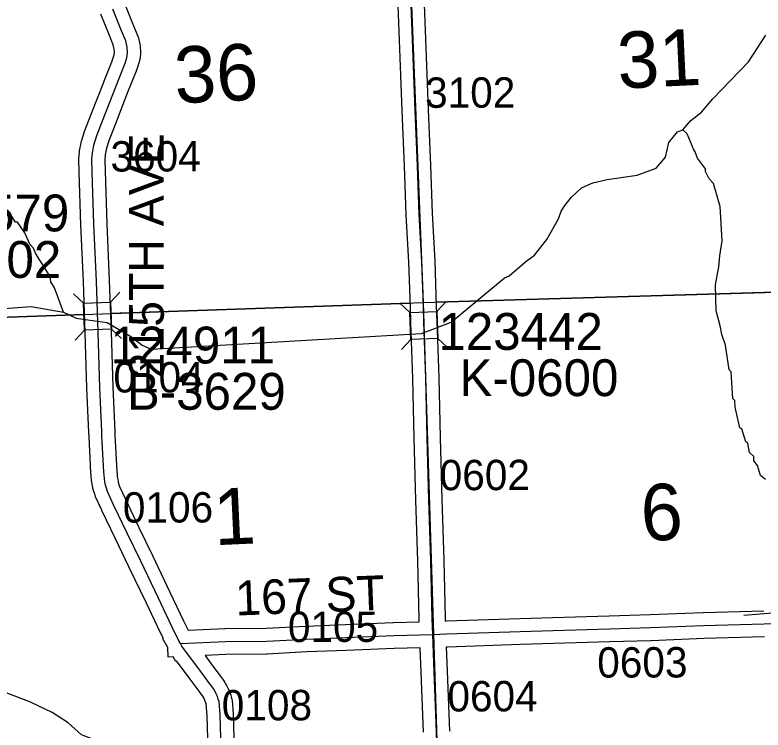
# Model space of a CAD drawing. Extents: x 128.7 to 185.5, y -21.4 to 12.6.
# Drawn here: x 145.06 to 146.785, y -2.33 to -0.681 of the extents above; entities that cross this region are included whole.
import ezdxf

# ---------------------------------------------------------------- set-up
doc = ezdxf.new("R2010")
doc.units = 0
for name, color, linetype in [('tdCoHydroRiver', 7, 'Continuous'), ('tdCoSecRdNmbr', 7, 'Continuous'), ('tdCoSecRdTxt', 7, 'Continuous'), ('tdCoSecRteBand', 7, 'Continuous'), ('tdCoSecRteCL', 7, 'Continuous'), ('tdCoSectLine', 7, 'Continuous'), ('tdCoSectLinePart', 7, 'Continuous'), ('tdCoSectNmbr', 7, 'Continuous'), ('tdCoStrucSec', 7, 'Continuous'), ('tdCoStrucSecCoName', 7, 'Continuous'), ('tdCoStrucSecFHWANum', 7, 'Continuous'), ('tdCoSurfGravel', 7, 'Continuous'), ('tdCoTwpBndry', 7, 'Continuous'), ('tdCoTwpBndryShd', 7, 'Continuous')]:
    doc.layers.add(name, color=color, linetype=linetype)

msp = doc.modelspace()

# ---------------------------------------------------------------- linework, layer by layer
at = {"layer": 'tdCoHydroRiver'}
for points in [[(145.0233, -1.3591), (145.0973, -1.3536), (145.1719, -1.3669), (145.2007, -1.3801), (145.2494, -1.3872), (145.2721, -1.3904), (145.3284, -1.4233), (145.3527, -1.443), (145.3735, -1.4518), (145.9972, -1.4155), (146.0658, -1.3896), (146.1887, -1.2877), (146.1996, -1.2827), (146.238, -1.2498), (146.258, -1.235), (146.2868, -1.1993), (146.3136, -1.1511), (146.3194, -1.1335), (146.3239, -1.1271), (146.3284, -1.1206), (146.3435, -1.1012), (146.3665, -1.0799), (146.393, -1.068), (146.4259, -1.0606), (146.495, -1.0504), (146.5386, -1.0348), (146.5599, -1.0089), (146.5682, -0.9754), (146.588, -0.9511), (146.6004, -0.946), (146.6187, -0.9249), (146.6433, -0.9051), (146.6691, -0.8743), (146.7515, -0.7895), (146.7921, -0.7282)], [(146.791, -1.7524), (146.7797, -1.7433), (146.7726, -1.7199), (146.7643, -1.7091), (146.764, -1.6997), (146.7543, -1.6905), (146.7504, -1.6686), (146.7455, -1.6656), (146.7367, -1.6359), (146.7319, -1.6329), (146.7208, -1.5859), (146.7203, -1.5701), (146.7154, -1.5655), (146.7118, -1.5041), (146.707, -1.4995), (146.6988, -1.443), (146.6901, -1.418), (146.6863, -1.3977), (146.6772, -1.3632), (146.6753, -1.3033), (146.6834, -1.262), (146.6857, -1.2367), (146.6909, -1.2018), (146.6867, -1.1231), (146.6708, -1.0699), (146.6609, -1.0592), (146.6525, -1.0421), (146.6523, -1.0358), (146.6341, -1.0112), (146.6289, -0.9971), (146.6256, -0.9925), (146.6102, -0.9551), (146.6004, -0.946)], [(145.1719, -1.3669), (145.1511, -1.3108), (145.1427, -1.2968), (145.1407, -1.2843), (145.1075, -1.2317), (145.1023, -1.2193), (145.0941, -1.2101), (145.0822, -1.1836), (145.0656, -1.1589), (145.0609, -1.1591), (145.0442, -1.1328)], [(146.7413, -2.065), (146.8074, -2.0596)], [(145.5048, -2.4228), (145.3677, -2.4304), (145.3597, -2.4275), (145.3461, -2.398), (145.33, -2.3859), (145.2133, -2.3408), (145.1824, -2.3134), (145.1453, -2.2894), (145.0956, -2.2657), (144.9806, -2.2222)]]:
    msp.add_lwpolyline(points, dxfattribs=at)
at = {"layer": 'tdCoSecRteBand'}
for points in [[(145.313, -0.6567), (145.3332, -0.7062), (145.3333, -0.7062), (145.3333, -0.7062), (145.3429, -0.7299), (145.3437, -0.7321), (145.3443, -0.7343), (145.3477, -0.7488), (145.3483, -0.7514), (145.3485, -0.754), (145.3492, -0.7669), (145.3494, -0.7697), (145.349, -0.7725), (145.3475, -0.7838), (145.3472, -0.7865), (145.3464, -0.7891), (145.3424, -0.8014), (145.3423, -0.8019), (145.3421, -0.8023), (145.3394, -0.8099), (145.3392, -0.8106), (145.3389, -0.8112), (145.32, -0.8578), (145.2913, -0.9321), (145.2912, -0.9321), (145.2912, -0.9322), (145.2768, -0.9689), (145.2708, -0.9883), (145.2679, -1.0039), (145.2672, -1.0145), (145.2676, -1.0418), (145.2718, -1.1628), (145.2772, -1.2936), (145.2772, -1.2937), (145.2772, -1.2938), (145.2814, -1.4119), (145.2814, -1.4119), (145.2814, -1.412), (145.2856, -1.5389), (145.2898, -1.6414), (145.2903, -1.6509), (145.2947, -1.7329), (145.2947, -1.7332), (145.2948, -1.7334), (145.295, -1.7403), (145.2956, -1.7463), (145.2965, -1.7523), (145.2977, -1.7582), (145.2993, -1.764), (145.3009, -1.7689), (145.3144, -1.798), (145.3456, -1.8634), (145.3766, -1.928), (145.3767, -1.928), (145.3767, -1.928), (145.4169, -2.0118), (145.4169, -2.0119), (145.4169, -2.0119), (145.4486, -2.0782), (145.4593, -2.0999)], [(145.4593, -2.0999), (145.5437, -2.0961), (145.5441, -2.0961), (145.5446, -2.0961), (145.6387, -2.0949), (145.7302, -2.0902), (145.7303, -2.0902), (145.7305, -2.0902), (145.8222, -2.0865), (145.9322, -2.082), (145.9324, -2.082), (145.9326, -2.082), (145.9921, -2.0804), (145.9918, -2.0739), (145.9918, -2.0736), (145.9918, -2.0733), (145.9891, -1.9405), (145.9844, -1.8002), (145.9844, -1.8001), (145.9844, -1.8), (145.9802, -1.6573), (145.9802, -1.6571), (145.9802, -1.657), (145.9775, -1.5194), (145.9728, -1.3901), (145.9728, -1.3901), (145.9728, -1.39), (145.9717, -1.3547), (145.9684, -1.2515), (145.9622, -1.1422), (145.9622, -1.1419), (145.9622, -1.1416), (145.958, -1.0302), (145.9528, -0.9027), (145.9528, -0.9027), (145.9528, -0.9027), (145.9479, -0.7797), (145.9479, -0.7796), (145.9479, -0.7796), (145.9435, -0.6595)], [(146.0034, -0.6572), (146.0079, -0.7773), (146.0128, -0.9003), (146.018, -1.0278), (146.018, -1.0278), (146.018, -1.0279), (146.0222, -1.1391), (146.0283, -1.2485), (146.0283, -1.2489), (146.0283, -1.2493), (146.0316, -1.3528), (146.0328, -1.388), (146.0375, -1.5174), (146.0375, -1.5177), (146.0375, -1.5179), (146.0402, -1.6556), (146.0444, -1.7982), (146.049, -1.9387), (146.0491, -1.9389), (146.0491, -1.9391), (146.0518, -2.0717), (146.0521, -2.0787)], [(145.5048, -2.3497), (145.5029, -2.2966), (145.5007, -2.2699), (145.5001, -2.2677), (145.4986, -2.2636), (145.4969, -2.2596), (145.4949, -2.2557), (145.4927, -2.252), (145.4902, -2.2484), (145.487, -2.2442), (145.4867, -2.2439), (145.4865, -2.2436), (145.4638, -2.2128), (145.4325, -2.1706), (145.4307, -2.1717), (145.4247, -2.1614), (145.4129, -2.162), (145.4119, -2.1394), (145.4005, -2.1198), (145.4019, -2.119), (145.3947, -2.1047), (145.3946, -2.1045), (145.3945, -2.1043), (145.3627, -2.0378), (145.3226, -1.9539), (145.2915, -1.8893), (145.2915, -1.8893), (145.2915, -1.8893), (145.2601, -1.8237), (145.2601, -1.8235), (145.26, -1.8234), (145.2457, -1.7925), (145.245, -1.7909), (145.2444, -1.7893), (145.242, -1.7819), (145.2417, -1.7811), (145.2415, -1.7803), (145.2395, -1.7729), (145.2393, -1.7721), (145.2391, -1.7712), (145.2376, -1.7637), (145.2374, -1.7629), (145.2373, -1.762), (145.2361, -1.7544), (145.236, -1.7536), (145.2359, -1.7528), (145.2352, -1.7451), (145.2351, -1.7442), (145.2351, -1.7434), (145.2348, -1.7359), (145.2304, -1.654), (145.2304, -1.654), (145.2304, -1.6539), (145.2299, -1.6442), (145.2299, -1.6441), (145.2299, -1.644), (145.2257, -1.5412), (145.2257, -1.5411), (145.2257, -1.541), (145.2215, -1.414), (145.2173, -1.296), (145.2119, -1.1651), (145.2119, -1.165), (145.2119, -1.1649), (145.2077, -1.0436), (145.2077, -1.0433), (145.2077, -1.0431), (145.2072, -1.0142), (145.2071, -1.0129), (145.2072, -1.0115), (145.2082, -0.998), (145.2083, -0.9964), (145.2086, -0.9948), (145.2121, -0.9758), (145.2124, -0.974), (145.213, -0.9723), (145.2199, -0.9501), (145.2202, -0.949), (145.2206, -0.948), (145.2353, -0.9103), (145.2642, -0.8359), (145.2643, -0.8357), (145.2643, -0.8355), (145.2831, -0.7893), (145.2854, -0.7827), (145.2884, -0.7734), (145.2892, -0.7675), (145.2887, -0.7601), (145.2864, -0.7504), (145.2777, -0.7289), (145.2575, -0.6793)], [(146.0521, -2.0787), (146.0553, -2.0786), (146.2239, -2.0732), (146.3001, -2.0707), (146.3002, -2.0707), (146.3002, -2.0707), (146.4304, -2.067), (146.5247, -2.064), (146.6471, -2.0589), (146.6473, -2.0589), (146.6476, -2.0588), (146.7872, -2.0554)], [(146.7886, -2.1154), (146.6493, -2.1188), (146.527, -2.124), (146.5269, -2.124), (146.5267, -2.124), (146.4322, -2.127), (146.4322, -2.127), (146.4322, -2.127), (146.302, -2.1307), (146.2259, -2.1331), (146.2259, -2.1331), (146.2259, -2.1331), (146.0572, -2.1386), (146.0571, -2.1386), (146.0571, -2.1386), (146.0546, -2.1386), (146.0569, -2.1939), (146.0569, -2.194), (146.0569, -2.1941), (146.0621, -2.3329)], [(146.0022, -2.3351), (145.997, -2.1964), (145.9946, -2.1407), (145.9946, -2.1403), (145.9942, -2.1403), (145.9344, -2.142), (145.8246, -2.1464), (145.7331, -2.1501), (145.6412, -2.1548), (145.6407, -2.1548), (145.6401, -2.1548), (145.5459, -2.1561), (145.498, -2.1582), (145.5121, -2.1771), (145.5121, -2.1771), (145.5121, -2.1772), (145.5346, -2.2077), (145.5382, -2.2123), (145.5388, -2.2131), (145.5393, -2.2138), (145.5428, -2.219), (145.5433, -2.2198), (145.5438, -2.2206), (145.547, -2.226), (145.5475, -2.2268), (145.5479, -2.2277), (145.5508, -2.2332), (145.5512, -2.2341), (145.5516, -2.235), (145.5541, -2.2407), (145.5544, -2.2416), (145.5548, -2.2425), (145.5569, -2.2484), (145.5572, -2.2492), (145.5575, -2.2502), (145.5592, -2.2562), (145.56, -2.2591), (145.5603, -2.2621), (145.5627, -2.2924), (145.5628, -2.2931), (145.5628, -2.2937), (145.5648, -2.3477)]]:
    msp.add_lwpolyline(points, dxfattribs=at)
at = {"layer": 'tdCoSecRteCL'}
for points in [[(146.0233, -2.1095), (146.0218, -2.0726), (146.0191, -1.9397), (146.0144, -1.7992), (146.0102, -1.6564), (146.0075, -1.5185), (146.0028, -1.3891), (146.0017, -1.3537), (145.9983, -1.2502), (145.9922, -1.1405), (145.988, -1.029), (145.9828, -0.9015), (145.9779, -0.7785), (145.9734, -0.6584), (145.9683, -0.5286), (145.9653, -0.4071), (145.9628, -0.3451)], [(145.4415, -2.1307), (145.4386, -2.1257), (145.4216, -2.0914), (145.3898, -2.0248), (145.3496, -1.941), (145.3185, -1.8763), (145.2872, -1.8107), (145.2729, -1.7799), (145.2705, -1.7726), (145.2685, -1.7651), (145.2669, -1.7576), (145.2658, -1.7499), (145.2651, -1.7423), (145.2648, -1.7345), (145.2603, -1.6524), (145.2599, -1.6427), (145.2557, -1.54), (145.2515, -1.413), (145.2473, -1.2948), (145.2418, -1.1639), (145.2377, -1.0426), (145.2372, -1.0137), (145.2381, -1.0002), (145.2416, -0.9812), (145.2485, -0.959), (145.2633, -0.9212), (145.2922, -0.8468), (145.3111, -0.7999), (145.3139, -0.7923), (145.3178, -0.7799), (145.3193, -0.7686), (145.3185, -0.7558), (145.3151, -0.7412), (145.3055, -0.7175), (145.2852, -0.668)], [(146.0233, -2.1095), (146.0562, -2.1086), (146.2249, -2.1031), (146.3011, -2.1007), (146.4313, -2.097), (146.5258, -2.094), (146.6483, -2.0888), (146.7879, -2.0854), (146.9452, -2.0819), (147.0195, -2.0804)], [(145.4415, -2.1307), (145.545, -2.1261), (145.6397, -2.1248), (145.7317, -2.1202), (145.8234, -2.1165), (145.9334, -2.112), (146.0233, -2.1095)], [(146.0618, -3.3563), (146.0615, -3.3461), (146.0583, -3.1979), (146.0533, -3.0443), (146.0489, -2.9158), (146.045, -2.7585), (146.0408, -2.6051), (146.0368, -2.4808), (146.0321, -2.334), (146.027, -2.1952), (146.0233, -2.1095)], [(145.5354, -2.3803), (145.5348, -2.3488), (145.5328, -2.2948), (145.5304, -2.2645), (145.5286, -2.2585), (145.5265, -2.2526), (145.524, -2.2469), (145.5212, -2.2413), (145.518, -2.2359), (145.5145, -2.2307), (145.5106, -2.2258), (145.488, -2.195), (145.4554, -2.1511), (145.4448, -2.1363), (145.4415, -2.1307)]]:
    msp.add_lwpolyline(points, dxfattribs=at)
at = {"layer": 'tdCoSectLine'}
for points in [[(145.9624, -0.3451), (146.001, -1.3445)], [(146.001, -1.3445), (147.0006, -1.3151)], [(144.999, -1.3795), (146.001, -1.3445)], [(146.001, -1.3445), (146.0324, -2.3549)]]:
    msp.add_lwpolyline(points, dxfattribs=at)
at = {"layer": 'tdCoSectLinePart'}
for points in [[(146.0312, -1.3436), (146.9704, -1.316)], [(145.2796, -1.3697), (145.9712, -1.3455)], [(144.999, -1.3795), (145.2194, -1.3718)]]:
    msp.add_lwpolyline(points, dxfattribs=at)
at = {"layer": 'tdCoStrucSec'}
for p, q in [((145.2174, -1.3456), (145.1945, -1.3243)), ((145.2799, -1.3434), (145.3013, -1.3205)), ((145.9703, -1.367), (145.9474, -1.3457)), ((146.0329, -1.3648), (146.0542, -1.3418)), ((145.2196, -1.4082), (145.1983, -1.4311)), ((145.2822, -1.406), (145.3051, -1.4273)), ((145.9726, -1.4296), (145.9512, -1.4525)), ((146.0351, -1.4273), (146.058, -1.4486))]:
    msp.add_line(p, q, dxfattribs=at)
for points in [[(145.2196, -1.4082), (145.2174, -1.3456), (145.2799, -1.3434), (145.2822, -1.406)], [(145.9726, -1.4296), (145.9703, -1.367), (146.0329, -1.3648), (146.0351, -1.4273)]]:
    msp.add_lwpolyline(points, close=True, dxfattribs=at)
at = {"layer": 'tdCoSurfGravel'}
for points in [[(146.0017, -1.3537), (145.9983, -1.2502), (145.9922, -1.1405), (145.988, -1.029), (145.9828, -0.9015), (145.9779, -0.7785), (145.9734, -0.6584), (145.9683, -0.5286), (145.9653, -0.4071), (145.9628, -0.3451)], [(145.5348, -2.3488), (145.5328, -2.2948), (145.5304, -2.2645), (145.5286, -2.2585), (145.5265, -2.2526), (145.524, -2.2469), (145.5212, -2.2413), (145.518, -2.2359), (145.5145, -2.2307), (145.5106, -2.2258), (145.488, -2.195), (145.4554, -2.1511), (145.4448, -2.1363), (145.4415, -2.1307), (145.4386, -2.1257), (145.4216, -2.0914), (145.3898, -2.0248), (145.3496, -1.941), (145.3185, -1.8763), (145.2872, -1.8107), (145.2729, -1.7799), (145.2705, -1.7726), (145.2685, -1.7651), (145.2669, -1.7576), (145.2658, -1.7499), (145.2651, -1.7423), (145.2648, -1.7345), (145.2603, -1.6524), (145.2599, -1.6427), (145.2557, -1.54), (145.2515, -1.413), (145.2473, -1.2948), (145.2418, -1.1639), (145.2377, -1.0426), (145.2372, -1.0137), (145.2381, -1.0002), (145.2416, -0.9812), (145.2485, -0.959), (145.2633, -0.9212), (145.2922, -0.8468), (145.3111, -0.7999), (145.3139, -0.7923), (145.3178, -0.7799), (145.3193, -0.7686), (145.3185, -0.7558), (145.3151, -0.7412), (145.3055, -0.7175), (145.2852, -0.668)], [(146.0233, -2.1095), (146.0218, -2.0726), (146.0191, -1.9397), (146.0144, -1.7992), (146.0102, -1.6564), (146.0075, -1.5185), (146.0028, -1.3891), (146.0017, -1.3537)], [(145.4415, -2.1307), (145.545, -2.1261), (145.6397, -2.1248), (145.7317, -2.1202), (145.8234, -2.1165), (145.9334, -2.112), (146.0233, -2.1095), (146.0562, -2.1086), (146.2249, -2.1031), (146.3011, -2.1007), (146.4313, -2.097), (146.5258, -2.094), (146.6483, -2.0888), (146.7879, -2.0854), (146.9452, -2.0819), (147.0195, -2.0804)], [(146.0907, -4.356), (146.0889, -4.2961), (146.0852, -4.1636), (146.0812, -4.0346), (146.0778, -3.9123), (146.0743, -3.7937), (146.0689, -3.6213), (146.0649, -3.4756), (146.0618, -3.3563), (146.0615, -3.3461), (146.0583, -3.1979), (146.0533, -3.0443), (146.0489, -2.9158), (146.045, -2.7585), (146.0408, -2.6051), (146.0368, -2.4808), (146.0321, -2.334), (146.027, -2.1952), (146.0233, -2.1095)]]:
    msp.add_lwpolyline(points, dxfattribs=at)
at = {"layer": 'tdCoTwpBndry'}
for points in [[(146.9707, -1.316), (146.031, -1.3436)], [(145.971, -1.3455), (145.2796, -1.3697)], [(145.2196, -1.3718), (144.999, -1.3795), (144.7785, -1.3874)]]:
    msp.add_lwpolyline(points, dxfattribs=at)
at = {"layer": 'tdCoTwpBndryShd'}
for points in [[(145.7753, 4.6779), (145.8126, 3.6695), (145.8481, 2.667), (145.8861, 1.6603), (145.9237, 0.6571), (145.9624, -0.3451), (146.001, -1.3445), (146.0324, -2.3549), (146.0614, -3.3563), (146.0903, -4.356), (146.1189, -5.3582), (146.1498, -6.358), (146.1796, -7.3579)], [(133.9673, -1.6731), (134.9785, -1.6501), (135.9787, -1.6285), (136.9783, -1.606), (136.9908, -1.6057), (137.9843, -1.5842), (138.9859, -1.5598), (139.9867, -1.5369), (141.001, -1.5077), (142.0055, -1.4764), (143.0036, -1.4478), (143.9967, -1.4154), (144.999, -1.3795), (146.001, -1.3445), (147.0006, -1.3151), (147.9961, -1.2801), (149.0001, -1.2471), (150.0007, -1.2153), (150.9999, -1.1762), (152.001, -1.1385), (152.9972, -1.0884), (154.0014, -1.05)]]:
    msp.add_lwpolyline(points, dxfattribs=at)

# ---------------------------------------------------------------- texts
at = {"layer": 'tdCoSecRdNmbr'}
for s, rotation, p in [('3102', 0.111, (146.0057, -0.8954)), ('3604', 0.1104, (145.28, -1.0424)), ('0104', 0.1104, (145.2868, -1.5518)), ('0602', 0.111, (146.0394, -1.7772)), ('0106', 0.1104, (145.3086, -1.8518)), ('0105', 0.1107, (145.6893, -2.1272)), ('0603', 0.1112, (146.4029, -2.2092)), ('0604', 0.111, (146.0572, -2.2872)), ('0108', 0.1106, (145.5367, -2.3079))]:
    msp.add_text(s, height=0.07, rotation=rotation, dxfattribs=at).set_placement(p)
at = {"layer": 'tdCoSecRdTxt'}
for s, rotation, p in [('215TH AVE', 90.0735, (145.403, -1.5193)), ('167 ST', 2.1983, (145.5694, -2.0661))]:
    msp.add_text(s, height=0.08, rotation=rotation, dxfattribs=at).set_placement(p)
at = {"layer": 'tdCoSectNmbr'}
for s, rotation, p in [('31', 2.6637, (146.4518, -0.8512)), ('36', 2.6629, (145.4298, -0.8852)), ('6', 2.6637, (146.5059, -1.8946)), ('1', 2.6629, (145.5204, -1.9041))]:
    msp.add_text(s, height=0.13, rotation=rotation, dxfattribs=at).set_placement(p)
at = {"layer": 'tdCoStrucSecCoName'}
for s, p in [('B-3579', (144.8183, -1.1803)), ('K-0600', (146.0851, -1.5602)), ('B-3629', (145.3178, -1.5916))]:
    msp.add_text(s, height=0.085, dxfattribs=at).set_placement(p)
at = {"layer": 'tdCoStrucSecFHWANum'}
for s, p in [('124902', (144.7871, -1.2876)), ('123442', (146.0365, -1.4535)), ('124911', (145.2802, -1.4849))]:
    msp.add_text(s, height=0.085, dxfattribs=at).set_placement(p)

doc.saveas('drawing.dxf')
